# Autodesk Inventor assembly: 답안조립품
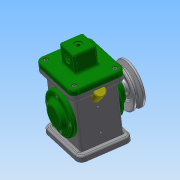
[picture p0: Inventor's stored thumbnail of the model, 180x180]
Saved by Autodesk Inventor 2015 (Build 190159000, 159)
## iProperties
Created: 2017-08
Part Number: 답안조립품
Document SubType Name: Assembly
Designer: owner
Author: owner
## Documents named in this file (16)
- C:\Users\owner\Desktop\470807V1008\답안조립품.iam
- C:\Users\owner\Desktop\470807V1008\1.본체.ipt
- C:\Users\owner\Desktop\470807V1008\편심축.ipt
- C:\Users\owner\Desktop\470807V1008\뒤커버.ipt
- C:\Users\owner\Desktop\470807V1008\앞커버.ipt
- C:\Users\owner\Desktop\470807V1008\베어링 17 x 40 x 12.ipt
- C:\Users\owner\Desktop\470807V1008\링크.ipt
- C:\Users\owner\Desktop\470807V1008\클레비스 핀 6 x 22.ipt
- 클레비스 핀 6 x 22.ipt
- C:\Users\owner\Desktop\470807V1008\슬라이더.ipt
- C:\Users\owner\Desktop\470807V1008\키 4 x 4 x 12.ipt
- C:\Users\owner\Desktop\470807V1008\V-벨트풀리.ipt
- C:\Users\owner\Desktop\470807V1008\와셔 4x16.ipt
- C:\Users\owner\Desktop\470807V1008\볼트 M4 x 10.ipt
- C:\Users\owner\Desktop\470807V1008\볼트 M4 x 8.ipt
- C:\Users\owner\Desktop\470807V1008\덮개.ipt
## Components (2 placed, 2 different names)
1. 1.본체:1
2. V-벨트풀리:1 — 각도:1, 플러쉬:2
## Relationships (2: Angle 1, Flush 1)
- 각도:1 [Angle]: V-벨트풀리:1
- 플러쉬:2 [Flush]: V-벨트풀리:1
